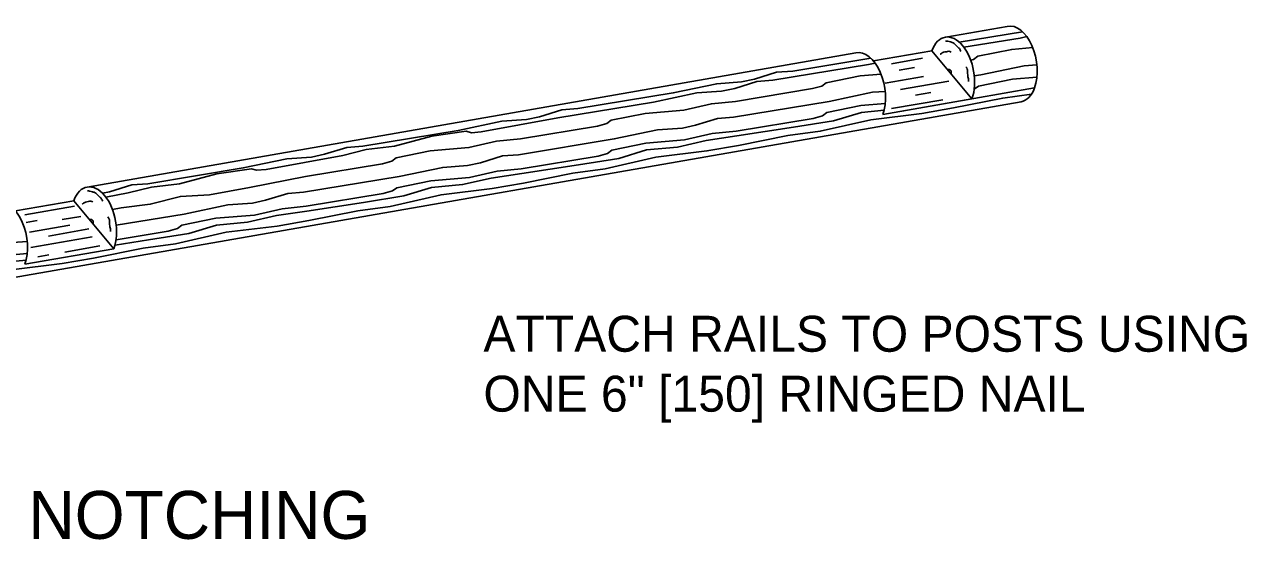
# Model space of a CAD drawing. Extents: x 49991 to 50288, y 49919 to 50011.
# Drawn here: x 50012.585 to 50014.624, y 49991.256 to 49992.116 of the extents above; entities that cross this region are included whole.
import ezdxf

# ---------------------------------------------------------------- set-up
doc = ezdxf.new("R2010")
doc.units = 0
doc.layers.add('Level 1', color=7, linetype='Continuous')
doc.layers.add('Level 2', color=7, linetype='Continuous')

msp = doc.modelspace()

# ---------------------------------------------------------------- linework, layer by layer
at = {"layer": 'Level 1'}
for p, q in [((50014.122182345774, 49992.09460711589), (50014.22503234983, 49992.11257560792)), ((50012.689545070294, 49991.844316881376), (50013.97203163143, 49992.06837471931)), ((50014.09905772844, 49992.07179988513), (50014.00162121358, 49992.05478777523)), ((50014.00163978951, 49992.05478112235), (50014.09905772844, 49992.07179988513)), ((50014.03174491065, 49992.0502808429), (50014.083719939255, 49992.05935537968)), ((50014.09906991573, 49992.07180201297), (50014.16596516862, 49991.9915178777)), ((50014.04471728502, 49992.03952707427), (50014.070215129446, 49992.043961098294)), ((50014.02107927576, 49992.01779899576), (50014.08517732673, 49992.0289939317)), ((50014.04690020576, 49992.00703343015), (50014.12718067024, 49992.021032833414)), ((50014.01737618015, 49991.96555414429), (50014.27039430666, 49992.00975601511)), ((50014.071848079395, 49991.99756854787), (50014.09734592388, 49992.0020025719)), ((50011.07515827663, 49991.43285974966), (50014.2479885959, 49991.986852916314)), ((50014.01737294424, 49991.965560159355), (50014.16596516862, 49991.9915178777)), ((50014.0317027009, 49991.97522271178), (50014.11715989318, 49991.99014857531)), ((50012.66717761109, 49991.82165266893), (50012.56974109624, 49991.80464055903)), ((50012.66845761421, 49991.81233249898), (50012.585501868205, 49991.79781371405)), ((50012.667189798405, 49991.82165479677), (50012.7340850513, 49991.7413706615)), ((50012.60602089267, 49991.78831823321), (50012.58752587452, 49991.785115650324)), ((50012.67880253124, 49991.7954941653), (50012.647897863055, 49991.79012041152)), ((50012.660755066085, 49991.78097695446), (50012.5933163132, 49991.769224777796)), ((50012.69214250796, 49991.77443078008), (50012.62491433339, 49991.762658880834)), ((50012.69811307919, 49991.76150299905), (50012.59545392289, 49991.743572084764)), ((50012.58549282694, 49991.71541294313), (50012.7340850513, 49991.7413706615)), ((50012.625702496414, 49991.731083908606), (50012.60723025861, 49991.72786285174)), ((50012.71076686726, 49991.74617728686), (50012.652385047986, 49991.73595437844))]:
    msp.add_line(p, q, dxfattribs=at)
for points in [[(50014.144857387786, 49992.08626510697), (50014.25023205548, 49992.10365327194)], [(50014.15264632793, 49992.07768305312), (50014.246305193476, 49992.093130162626), (50014.2574036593, 49992.095477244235)], [(50014.16406066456, 49992.055912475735), (50014.16844913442, 49992.05712403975), (50014.17564014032, 49992.06254551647), (50014.23243719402, 49992.074166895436), (50014.267349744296, 49992.07710229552)], [(50013.86686161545, 49992.037941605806), (50013.99721392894, 49992.05945140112)], [(50013.508103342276, 49991.97521983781), (50013.66757742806, 49992.001604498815), (50013.74011135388, 49992.01668270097), (50013.781298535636, 49992.01983519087), (50013.80312848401, 49992.02444934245), (50013.8400761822, 49992.035854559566), (50013.86686161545, 49992.037941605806)], [(50013.77127363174, 49991.98742738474), (50013.89988555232, 49992.00863039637), (50013.91543100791, 49992.0129221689), (50013.92262201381, 49992.01834364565), (50013.9794190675, 49992.029965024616), (50014.014331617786, 49992.03290042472)], [(50013.833824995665, 49992.02262829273), (50013.993287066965, 49992.0489282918), (50014.00438553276, 49992.051275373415)], [(50014.16994414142, 49992.029792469), (50014.180667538, 49992.03156298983), (50014.25326119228, 49992.04666827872), (50014.27434059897, 49992.048284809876)], [(50013.47506241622, 49991.95994777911), (50013.63451802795, 49991.98630965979), (50013.70705195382, 49992.00138786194), (50013.74826406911, 49992.004501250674), (50013.7700733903, 49992.00911324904), (50013.807080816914, 49992.02054555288), (50013.833824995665, 49992.02262829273)], [(50014.16974522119, 49992.00755399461), (50014.176720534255, 49992.012842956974), (50014.23356314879, 49992.024427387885), (50014.27440947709, 49992.0278831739)], [(50013.76831325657, 49991.96105341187), (50013.92764941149, 49991.98736111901), (50014.00024306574, 49992.002466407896), (50014.02132247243, 49992.00408293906)], [(50014.135081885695, 49991.97640160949), (50014.21750089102, 49991.99286615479), (50014.26522159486, 49991.99934884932)], [(50013.14939187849, 49991.91264891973), (50013.30887457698, 49991.938951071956), (50013.3814020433, 49991.9540911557), (50013.42255227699, 49991.957198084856), (50013.44438653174, 49991.96177098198), (50013.481393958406, 49991.97320328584), (50013.508103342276, 49991.97521983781)], [(50013.41262835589, 49991.92482167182), (50013.54124242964, 49991.94600405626), (50013.556721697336, 49991.95033062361), (50013.563976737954, 49991.95573793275), (50013.62077163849, 49991.96737993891), (50013.685181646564, 49991.972789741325), (50013.731351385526, 49991.98334348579), (50013.77127363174, 49991.98742738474)], [(50013.77235833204, 49991.93768357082), (50013.90088989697, 49991.958857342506), (50013.91649508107, 49991.963176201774), (50013.923702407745, 49991.968641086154), (50013.98054502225, 49991.98022551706), (50014.02139135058, 49991.9836813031)], [(50013.7736888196, 49991.9297318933), (50013.86818490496, 49991.944162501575), (50013.9351429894, 49991.954926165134), (50013.98157411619, 49991.96896862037), (50014.019479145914, 49991.97248211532)], [(50013.7764452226, 49991.9137133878), (50013.85880234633, 49991.930171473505), (50013.91276142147, 49991.937618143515), (50013.99735820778, 49991.95679140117), (50014.08257270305, 49991.967250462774), (50014.135081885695, 49991.97640160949)], [(50013.47506241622, 49991.95994777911), (50013.34691084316, 49991.93633228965), (50013.33075793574, 49991.93506319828), (50013.322211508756, 49991.93763250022), (50013.26481811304, 49991.929326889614), (50013.20235556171, 49991.91265179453), (50013.15534763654, 49991.90693161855), (50013.11645068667, 49991.897220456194)], [(50013.409591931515, 49991.89837720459), (50013.56905830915, 49991.92463594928), (50013.64154236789, 49991.93979235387), (50013.68273600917, 49991.94288296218), (50013.70455734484, 49991.94757962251), (50013.74163526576, 49991.95893587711), (50013.76831325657, 49991.96105341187)], [(50013.41365978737, 49991.87498888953), (50013.542193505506, 49991.896142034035), (50013.55777375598, 49991.90049999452), (50013.565051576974, 49991.90588882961), (50013.62182154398, 49991.91756993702), (50013.686208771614, 49991.922998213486), (50013.7323557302, 49991.93357043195), (50013.77235833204, 49991.93768357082)], [(50012.79067485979, 49991.84993145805), (50012.95013477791, 49991.87625208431), (50013.022657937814, 49991.891433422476), (50013.06381463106, 49991.89447847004), (50013.08568152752, 49991.89913818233), (50013.1226498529, 49991.910545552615), (50013.14939187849, 49991.91264891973)], [(50013.05396245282, 49991.8622138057), (50013.182562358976, 49991.88333215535), (50013.19813614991, 49991.88775199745), (50013.205312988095, 49991.89310943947), (50013.26212636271, 49991.904774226), (50013.32653421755, 49991.91020465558), (50013.3727082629, 49991.92071714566), (50013.41262835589, 49991.92482167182)], [(50013.41498812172, 49991.867057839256), (50013.50944295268, 49991.88148414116), (50013.576479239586, 49991.892297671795), (50013.62297224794, 49991.90634658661), (50013.67469381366, 49991.91105745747), (50013.72261811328, 49991.92198202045), (50013.7736888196, 49991.9297318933)], [(50013.41780425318, 49991.85106642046), (50013.50018415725, 49991.86750603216), (50013.55410197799, 49991.87494839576), (50013.63869015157, 49991.89420416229), (50013.72384922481, 49991.904594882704), (50013.7764452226, 49991.9137133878)], [(50013.11645068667, 49991.897220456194), (50012.98819597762, 49991.873594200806), (50012.97210279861, 49991.87235219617), (50012.96359762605, 49991.87492580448), (50012.90618790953, 49991.866576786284), (50012.84370042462, 49991.84994079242), (50012.79676299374, 49991.844144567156), (50012.75785958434, 49991.834495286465)], [(50013.0508130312, 49991.835653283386), (50013.21026648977, 49991.86203579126), (50013.28286229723, 49991.877120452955), (50013.324051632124, 49991.88025231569), (50013.34589574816, 49991.88493050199), (50013.38286837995, 49991.896296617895), (50013.409591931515, 49991.89837720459)], [(50013.05497971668, 49991.81231698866), (50013.18350912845, 49991.833511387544), (50013.199126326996, 49991.837914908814), (50013.206385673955, 49991.84328096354), (50013.26314147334, 49991.854898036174), (50013.32754717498, 49991.86034909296), (50013.37370059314, 49991.870859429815), (50013.41365978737, 49991.87498888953)], [(50012.715251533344, 49991.83396778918), (50012.72698298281, 49991.836443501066), (50012.763930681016, 49991.84784871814), (50012.79067485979, 49991.84993145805)], [(50013.05396245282, 49991.8622138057), (50012.9602270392, 49991.84369220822), (50012.893622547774, 49991.831339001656), (50012.8451897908, 49991.828681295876), (50012.7948005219, 49991.81560189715), (50012.74602942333, 49991.809593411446), (50012.731810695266, 49991.8067746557)], [(50013.05636993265, 49991.80439239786), (50013.150785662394, 49991.81879376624), (50013.21781979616, 49991.82962792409), (50013.264255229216, 49991.84362912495), (50013.31598019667, 49991.8485071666), (50013.36395866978, 49991.85931227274), (50013.41498812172, 49991.867057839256)], [(50013.059183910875, 49991.7884216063), (50013.14148130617, 49991.804852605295), (50013.195436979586, 49991.8121321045), (50013.28004918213, 49991.83155719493), (50013.36518762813, 49991.84194576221), (50013.41780425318, 49991.85106642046)], [(50012.75785958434, 49991.834495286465), (50012.72068571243, 49991.827653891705)], [(50012.73798532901, 49991.78058272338), (50012.85168740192, 49991.799395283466), (50012.924262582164, 49991.814477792), (50012.965410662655, 49991.81760534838), (50012.98723415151, 49991.822281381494), (50013.02416768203, 49991.83362256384), (50013.0508130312, 49991.835653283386)], [(50012.737745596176, 49991.75649677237), (50012.82493004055, 49991.77087087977), (50012.84048966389, 49991.77522668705), (50012.84766865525, 49991.78056350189), (50012.904479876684, 49991.792248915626), (50012.9688692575, 49991.79765656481), (50013.01508240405, 49991.808193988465), (50013.05497971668, 49991.81231698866)], [(50012.70037792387, 49991.72575741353), (50012.78282186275, 49991.74218285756), (50012.83681017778, 49991.749549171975), (50012.92141682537, 49991.768827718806), (50013.00656943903, 49991.779280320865), (50013.059183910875, 49991.7884216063)], [(50012.73600588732, 49991.74755815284), (50012.792107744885, 49991.756101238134), (50012.859131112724, 49991.76703853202), (50012.90553605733, 49991.78093229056), (50012.957380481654, 49991.78586450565), (50013.00534048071, 49991.7966468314), (50013.05636993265, 49991.80439239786)], [(50012.33357019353, 49991.710384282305), (50012.493007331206, 49991.73672338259), (50012.56559667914, 49991.75186992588), (50012.58947367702, 49991.75365337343)], [(50012.3376315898, 49991.68705784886), (50012.46628907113, 49991.70822391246), (50012.48179111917, 49991.71253200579), (50012.48902553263, 49991.71793716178), (50012.54582043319, 49991.72957916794), (50012.58948304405, 49991.73328844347)], [(50012.33896423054, 49991.67908554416), (50012.43353296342, 49991.69341947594), (50012.500426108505, 49991.70440573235), (50012.54688647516, 49991.71836783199), (50012.58754041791, 49991.72210379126)], [(50012.34176188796, 49991.663071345), (50012.42418304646, 49991.67951526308), (50012.478014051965, 49991.686990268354), (50012.56265424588, 49991.706147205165), (50012.647767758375, 49991.71657487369), (50012.70037792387, 49991.72575741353)]]:
    msp.add_lwpolyline(points, dxfattribs=at)
for centre, start_param, end_param in [((50014.23691240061, 49992.04981277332), 3.9254893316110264, 6.306125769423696), ((50014.13248502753, 49992.03156384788), 3.9256121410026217, 7.063370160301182), ((50013.9838942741, 49992.00561090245), 3.9254893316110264, 6.306125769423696), ((50014.23689623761, 49992.049768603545), 3.1414661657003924, 3.926391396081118), ((50012.700604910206, 49991.781416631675), 3.9256121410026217, 7.063370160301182), ((50012.552010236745, 49991.75545298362), 3.925707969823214, 6.306125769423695)]:
    msp.add_ellipse(centre, major_axis=(-0.011049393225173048, 0.06292576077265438), ratio=0.5774931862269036, start_param=start_param, end_param=end_param, dxfattribs=at)
for points in [[(50014.12179652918, 49992.088309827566), (50014.12555520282, 49992.08765958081), (50014.13030794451, 49992.08667520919), (50014.13303400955, 49992.08572950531), (50014.136080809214, 49992.084108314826), (50014.138122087, 49992.08213193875), (50014.140150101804, 49992.07988310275), (50014.14325469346, 49992.07730875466), (50014.14425362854, 49992.07632872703), (50014.14562407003, 49992.07438658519), (50014.14697875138, 49992.07179638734), (50014.14730900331, 49992.07082996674)], [(50014.11309689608, 49992.06600582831), (50014.114080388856, 49992.066703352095), (50014.118670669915, 49992.069401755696), (50014.123323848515, 49992.07027996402), (50014.12734261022, 49992.071026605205), (50014.13105330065, 49992.06961035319)], [(50014.12542764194, 49992.04016886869), (50014.12545743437, 49992.040192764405), (50014.125509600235, 49992.04023398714), (50014.1256646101, 49992.04034186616), (50014.12582562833, 49992.04042876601), (50014.12616275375, 49992.040546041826), (50014.12633764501, 49992.0405795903), (50014.12651548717, 49992.040600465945), (50014.12687680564, 49992.04059939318), (50014.12706179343, 49992.04058136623), (50014.12724417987, 49992.04055920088), (50014.12742487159, 49992.040531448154), (50014.12760477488, 49992.040496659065), (50014.12795929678, 49992.04041882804), (50014.128299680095, 49992.04034045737), (50014.12852798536, 49992.04028676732), (50014.12875487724, 49992.04022621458), (50014.12920192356, 49992.04007143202), (50014.129635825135, 49992.039849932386), (50014.12984628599, 49992.03970598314), (50014.12994962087, 49992.03962427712), (50014.13005158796, 49992.039535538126), (50014.13031150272, 49992.03928492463), (50014.13054700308, 49992.03902766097), (50014.130752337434, 49992.038767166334), (50014.13084650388, 49992.038630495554), (50014.13093598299, 49992.038489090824), (50014.13108469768, 49992.03820733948), (50014.13120097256, 49992.03791164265), (50014.13128148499, 49992.03760578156), (50014.13132441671, 49992.03728713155), (50014.131364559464, 49992.036533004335), (50014.13137830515, 49992.03578230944), (50014.131368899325, 49992.03503322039), (50014.13133958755, 49992.03428391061), (50014.13131754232, 49992.033826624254), (50014.13129582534, 49992.033369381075), (50014.131284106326, 49992.03314090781)], [(50014.160130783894, 49992.020515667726), (50014.16044444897, 49992.02337740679), (50014.15974202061, 49992.02638523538), (50014.15879456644, 49992.03366557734), (50014.158651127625, 49992.03559445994), (50014.158241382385, 49992.04119443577), (50014.15590127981, 49992.045012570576)], [(50012.68991641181, 49991.83816261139), (50012.6936750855, 49991.837512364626), (50012.69842782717, 49991.836527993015), (50012.70115389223, 49991.835582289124), (50012.70420069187, 49991.83396109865), (50012.70624196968, 49991.83198472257), (50012.70826998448, 49991.829735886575), (50012.711374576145, 49991.82716153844), (50012.71237351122, 49991.826181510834), (50012.71374395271, 49991.824239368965), (50012.71509863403, 49991.821649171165), (50012.71542888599, 49991.820682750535)], [(50012.68121677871, 49991.81585861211), (50012.68220027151, 49991.81655613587), (50012.68679055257, 49991.81925453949), (50012.691443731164, 49991.82013274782), (50012.69546249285, 49991.820879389), (50012.699173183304, 49991.81946313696)], [(50012.6935475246, 49991.79002165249), (50012.693577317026, 49991.7900455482), (50012.69362948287, 49991.79008677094), (50012.69378449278, 49991.79019464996), (50012.69394551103, 49991.79028154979), (50012.6942826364, 49991.79039882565), (50012.69445752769, 49991.790432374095), (50012.69463536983, 49991.79045324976), (50012.69499668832, 49991.79045217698), (50012.695181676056, 49991.79043415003), (50012.6953640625, 49991.790411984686), (50012.69554475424, 49991.79038423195), (50012.69572465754, 49991.79034944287), (50012.69607917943, 49991.79027161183), (50012.69641956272, 49991.79019324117), (50012.69664786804, 49991.790139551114), (50012.69687475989, 49991.790078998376), (50012.69732180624, 49991.78992421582), (50012.69775570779, 49991.78970271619), (50012.69796616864, 49991.78955876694), (50012.698069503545, 49991.78947706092), (50012.69817147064, 49991.78938832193), (50012.6984313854, 49991.78913770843), (50012.69866688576, 49991.788880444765), (50012.69887222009, 49991.78861995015), (50012.69896638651, 49991.78848327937), (50012.69905586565, 49991.78834187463), (50012.699204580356, 49991.788060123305), (50012.69932085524, 49991.78776442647), (50012.69940136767, 49991.78745856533), (50012.69944429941, 49991.78713991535), (50012.69948444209, 49991.78638578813), (50012.69949818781, 49991.78563509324), (50012.699488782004, 49991.78488600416), (50012.69945947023, 49991.784136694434), (50012.699437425, 49991.78367940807), (50012.69941570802, 49991.78322216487), (50012.69940398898, 49991.78299369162)], [(50012.72825066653, 49991.77036845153), (50012.72856433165, 49991.77323019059), (50012.72786190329, 49991.776238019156), (50012.72691444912, 49991.78351836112), (50012.72677101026, 49991.78544724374), (50012.72636126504, 49991.791047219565), (50012.72402116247, 49991.79486535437)]]:
    msp.add_spline(points, degree=3, dxfattribs=at)

# ---------------------------------------------------------------- texts
at = {"layer": 'Level 2'}
for s, height, p in [('ATTACH RAILS TO POSTS USING ', 0.05999999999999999, (50013.35076235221, 49991.56951967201)), ('ONE 6" [150] RINGED NAIL', 0.05999999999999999, (50013.35076235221, 49991.46951967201)), ('RAIL NOTCHING', 0.08000000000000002, (50012.32400377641, 49991.257199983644))]:
    msp.add_text(s, height=height, dxfattribs=at).set_placement(p)

doc.saveas('drawing.dxf')
